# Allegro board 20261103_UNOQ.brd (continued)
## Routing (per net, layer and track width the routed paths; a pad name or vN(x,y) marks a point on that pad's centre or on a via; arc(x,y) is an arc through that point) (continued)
VBAT: length 0.4
  TOP w0.203: 45.73,16.05 45.73,16.34 R603.2
  vias: v1(7.4,14.04) v1(7.4,13.81) v1(7.4,13.56) v1(7.62,40.3) v1(7.62,40.04) v1(7.62,39.79) v1(7.62,14.04) v1(7.62,13.81) v1(7.62,13.56) v1(7.87,40.3) v1(7.87,40.04) v1(7.87,39.79) v1(7.85,14.04) v1(7.85,13.81) v1(7.85,13.56) v1(8.13,40.3) v1(8.13,40.04) v1(8.13,39.79) v1(8.11,14.04) v1(8.11,13.81) v1(8.11,13.56) v2(45.72,15.72) v2(45.72,15.46) v2(45.73,15.23) v2(45.97,15.72) v2(45.97,15.46) v2(45.98,15.23) v2(46.19,15.71) v2(46.18,15.46) v2(46.19,15.24) v2(46.43,15.71) v2(46.42,15.46) v2(46.43,15.24) v3(45.72,15.72) v3(45.72,15.46) v3(45.73,15.23) v3(45.97,15.72) v3(45.97,15.46) v3(45.98,15.23) v3(46.19,15.71) v3(46.18,15.46) v3(46.19,15.24) v3(46.43,15.71) v3(46.42,15.46) v3(46.43,15.24) v4(6.49,40.57) v4(6.49,40.12) v4(6.89,40.56) v4(6.89,40.11) v4(7.29,40.56) v4(7.29,40.11) v4(13.89,7.37) v4(14.17,7.06) v4(14.43,6.68) v4(14.86,6.68) v4(15.32,6.68) v4(15.57,7.14) v4(45.85,14.96) v4(46.22,14.96) v4(46.59,14.96) v4(46.74,15.66) v4(46.74,15.3) v4(46.94,14.99) v5(7.62,40.3) v5(7.62,40.04) v5(7.62,39.79) v5(7.87,40.3) v5(7.87,40.04) v5(7.87,39.79) v5(8.13,40.3) v5(8.13,40.04) v5(8.13,39.79) v5(14.4,7.54) v5(14.43,7.26) v5(14.58,7.01) v5(14.68,7.52) v5(14.68,7.26) v5(14.81,7.01) v5(14.94,7.52) v5(14.94,7.26) v5(15.04,7.01) v5(15.19,7.52) v5(15.19,7.26) v5(15.29,7.01)
VBAT_CONN_VSNS_P: length 7.3
  S3 w0.064: v3(40.51,14.85) 43.82,14.85 45.11,16.14 46.52,16.14 46.61,16.23 46.61,16.46 46.53,16.54 46.36,16.54 46.29,16.47 v3(46.29,16.4)
VBUS_DIV8: length 4
  TOP w0.254: v3(33.06,51.55) 33.22,51.38 R3020.1 R3019.2
  G2 w0.203: v3(34.77,52.2) 34.82,52.25 34.92,52.25 v2(34.98,52.3)
  S3 w0.203: v3(33.06,51.55) 32.94,51.44 v4(32.94,51.16) ; v3(34.77,52.2) 34.62,52.04 v4(34.62,51.94)
  S6 w0.254: v4(32.94,51.16) 33.73,51.94 v4(34.62,51.94)
VBUS_POWER_SWITCH_DISABLE_N: length 47.9
  TOP w0.066: JCTL1.10 43.79,55.16 44.54,54.41 44.54,50.51 v3(44.34,50.31)
  S3 w0.064: v4(13.8,39.21) 15.06,37.95 17.76,37.95 18.3,37.41 19.88,37.41 v4(19.97,37.5) ; v3(44.34,50.31) 44.34,48.12 v4(43.48,47.26)
  S6 w0.064: v4(19.97,37.5) 19.97,38.21 22.15,40.39 33.25,40.39 34.65,41.78 36.58,41.78 37.46,42.66 39.29,42.66 41.58,44.95 41.58,45.31 43.48,47.21 v4(43.48,47.26) ; v5(14.05,39.07) 13.9,39.21 v4(13.8,39.21)
  G7 w0.064: v1(12.23,39.19) 12.79,38.63 13.61,38.63 v5(14.05,39.07)
AMUX_1_TP: length 6.5
  S3 w0.064: v3(39.66,8.85) 39.66,9.84 40.09,10.27 40.09,13.52 39.64,13.97 39.64,14.33 39.24,14.73 v3(39.24,14.81)
ANT_CH0: length 5.6
  TOP w0.066: ANT1.1 15.71,63.59 15.88,63.42 18.89,63.42 19.36,62.95 U2901.2
AUX_CTRL_1: length 13.1
  TOP w0.066: U3001.G1 34.32,51.54 33.83,51.05 v3(33.83,50.23) R3001.1 ; R3003.1 34.93,58.64 34.61,58.96 v3(34.2,58.96)
  S3 w0.064: v3(34.2,58.96) 33.84,58.61 33.84,58.02 33.4,57.58 33.4,56.18 32.55,55.32 32.55,52.56 33.32,51.78 33.32,50.75 33.83,50.24 v3(33.83,50.23)
AUX_CTRL_2: length 15.6
  TOP w0.066: 36.79,57.5 36.79,57.03 36.49,56.74 35.08,56.74 34.37,57.45 34.37,58.16 v3(34.09,58.44) ; U3001.H1 34.57,50.86 34.54,50.83 R3002.1 34.52,49.86 v3(34.14,50.24)
  S3 w0.064: v3(34.14,50.24) 33.5,50.88 33.5,51.93 32.72,52.71 32.72,55.28 33.53,56.09 33.53,57.48 34.09,58.03 v3(34.09,58.44)
BAT_ID: length 8
  S3 w0.064: v3(38.89,8.86) 38.89,9.05 38.74,9.19 38.75,9.2 38.75,9.8 v3(38.93,9.99) 39.55,9.99 39.95,10.39 39.95,13.48 39.48,13.95 39.48,14.33 39.18,14.63 39.12,14.63 38.69,15.06 v3(38.69,15.41)
BAT_THERM: length 6.8
  S3 w0.064: v3(39.26,14.28) 39.26,13.97 39.8,13.43 39.8,10.52 39.52,10.24 38.74,10.24 v3(38.5,10) 38.63,9.87 38.63,9.25 38.4,9.02 v3(38.4,8.85)
BOOT_CAP: length 5.1
  TOP w0.15: v2(40.95,14.28) 40.96,14.27 41.36,14.27 41.65,13.98 43.32,13.98 v2(43.36,14.01)
  G2 w0.2: v2(40.95,14.28) 40.97,14.3 41.36,14.3 41.65,14.01 v2(43.36,14.01)
BOOT_CONFIG0: length 2.7
  TOP w0.066: SOC1.AH9 22.97,36.88 R1304.1 R1303.2
BOOT_CONFIG1: length 2.4
  TOP w0.066: SOC1.AJ7 23.73,38.12 22.88,38.12 R1306.1 R1305.2
BOOT_CONFIG2: length 2.9
  TOP w0.066: R1307.2 R1308.1 22.88,37.55 23.37,37.55 23.89,37.03 24.32,37.03 SOC1.AH8
BOOT_CONFIG3: length 2.9
  TOP w0.066: R1309.2 R1310.1 22.86,38.68 23.5,38.68 24.1,38.08 SOC1.AH6
CBLPWR_N: length 5.4
  TOP w0.066: PMIC1.T10 36.65,14.56 v3(36.65,14.55)
  S3 w0.064: v3(36.65,14.55) 36.65,14.18 36.25,13.78 36.25,12.34 36.1,12.19 36.1,11.4 36.19,11.31 36.19,10.45 36.2,10.44 36.33,10.3 36.56,10.3 v3(36.93,9.93)
CC_OUT: length 4.2
  S3 w0.064: v3(35.28,21.95) 35.74,21.95 35.84,21.84 35.84,18.45 35.86,18.43 v3(35.86,18.24)
CCI_I2C_SCL0: length 29.7
  S3 w0.064: v4(13.96,52.83) 13.96,51.38 13.76,51.18 13.76,49.09 12.68,48.01 12.68,41.99 16.53,38.14 17.85,38.14 18.4,37.59 19.57,37.59 19.91,37.93 25.62,37.93 v3(26.17,38.48)
  S6 w0.064: v4(13.96,52.83) 14.18,53.05 v1(15.7,53.05)
  BOTTOM w0.066: R2607.1 15.35,53.4 v1(15.7,53.05)
CCI_I2C_SCL0_CONN: length 2.5
  BOTTOM w0.066: R2607.2 D26051.2 13.79,53.72 13.34,54.17 JMEDIA1.51
CCI_I2C_SCL1: length 47.6
  S3 w0.064: v4(14.05,58.79) 14.4,58.43 14.4,53.26 16.38,51.28 16.38,45.65 18.85,43.18 20.75,43.18 22.86,41.07 25.7,41.07 26.97,39.8 v3(26.97,39.68)
  S6 w0.064: v1(29.06,61.74) 28.57,61.74 26.57,59.75 26.57,57.86 26.03,57.31 14.62,57.31 14.32,57.62 14.32,58.48 14.05,58.75 v4(14.05,58.79)
  BOTTOM w0.066: R2611.1 30.19,62 R2610.1 29.31,62 29.06,61.76 v1(29.06,61.74)
CCI_I2C_SCL1_CONN: length 3.3
  BOTTOM w0.066: R2611.2 30.77,61.93 D26049.2 30.77,60.66 31.11,60.31 JMEDIA1.24
CCI_I2C_SDA0: length 27.8
  S3 w0.064: v3(26.17,38.88) 25.94,38.65 25.94,38.42 25.62,38.1 19.83,38.1 19.47,37.74 18.52,37.74 17.93,38.33 16.64,38.33 12.84,42.13 12.84,47.9 13.96,49.02 13.96,51.12 14.18,51.34 14.18,52.3 v4(14.36,52.48)
  S6 w0.064: v4(14.36,52.48) 14.4,52.48 v1(14.76,52.83)
  BOTTOM w0.066: R2608.1 14.75,52.84 v1(14.76,52.83)
CCI_I2C_SDA0_CONN: length 3.3
  BOTTOM w0.066: R2608.2 12.92,52.84 12.51,53.25 D26050.2 12.51,53.86 12.06,54.3 12.06,54.95
CCI_I2C_SDA1: length 49.7
  S3 w0.064: v3(26.57,38.88) 26.77,39.09 26.77,39.78 25.65,40.89 22.83,40.89 20.71,43.02 19.76,43.02 19.75,43.03 18.75,43.03 16.21,45.57 16.21,51.21 14.22,53.19 14.22,58.13 v4(14,58.36)
  S6 w0.064: v4(14,58.36) 14.16,58.19 14.16,57.55 14.54,57.17 26.12,57.17 26.7,57.75 26.7,59.67 28.48,61.45 v1(28.7,61.45)
  BOTTOM w0.066: v1(28.7,61.45) 28.7,61.73 28.94,61.97 29.06,61.97 29.48,62.39 30.62,62.39 30.77,62.54 R2609.1 31.08,62.74 R2612.1
CCI_I2C_SDA1_CONN: length 3.6
  BOTTOM w0.066: R2612.2 D26048.2 31.32,60.53 32.38,59.47 32.38,58.85
CDC_CP_FLY_N: length 2
  TOP w0.2: C501.2 42.19,19.59 41.52,18.91 PMIC1.A27 PMIC1.B26
CDC_CP_FLY_P: length 2.3
  TOP w0.2: C501.1 42.24,20.09 PMIC1.A25
CDC_CP_VNEG: length 2.9
  TOP w0.2: PMIC1.C27 41.73,18.24 42.16,18.68 42.61,18.68 43.18,19.25 C502.1 43.95,19.25 F501.1
CDC_PA_VNEG: length 4.7
  TOP w0.16: PMIC1.K24 40.67,17.25 40.82,17.4 41.23,17.4 ; PMIC1.F26 41.65,17.39 42.49,18.23 C503.1
  TOP w0.2: 41.23,17.4 PMIC1.F26 ; F501.2 43.91,18.23 C503.1
CSI0_A0_CLK_M: length 25.4
  TOP w0.058: SOC1.N2 30.65,39.68 v3(30.66,39.69)
  S3 w0.053: v3(30.66,39.69) 30.9,39.93 30.9,40.27 30.8,40.37 30.8,41.22 29.6,42.42 28.12,42.42 27.58,42.95 27.58,43.36 v4(27.76,43.54)
  S6 w0.053: v4(27.76,43.54) 27.76,43.77 v1(27.69,43.85)
  BOTTOM w0.058: JMEDIA1.33 24.26,54.95 24.2,54.89 24.2,53.97 24.3,53.88 25.14,53.88 25.32,53.69 25.32,53.31 U2610.7 U2610.4 25.35,52.08 25.35,51.57 27.59,49.33 27.59,48.83 27.45,48.7 26.9,48.7 26.84,48.64 26.84,48.52 26.9,48.46 27.45,48.46 27.59,48.32 27.59,48.1 27.45,47.96 26.9,47.96 26.84,47.9 26.84,47.78 26.9,47.73 27.45,47.73 27.59,47.59 27.59,47.36 27.45,47.22 26.9,47.22 26.84,47.16 26.84,47.05 26.9,46.99 27.45,46.99 27.59,46.85 27.59,46.62 27.45,46.49 26.9,46.49 26.84,46.43 26.84,46.31 26.9,46.25 27.45,46.25 27.59,46.12 27.59,44.18 27.69,44.08 v1(27.69,43.85)
CSI0_A1_LN1_P: length 25.2
  TOP w0.058: v3(30.27,39.61) 30.2,39.68 30.17,39.68
  S3 w0.05: 30.29,39.65 30.28,39.63
  S3 w0.053: 30.29,39.65 30.29,39.72 30.31,39.74 30.31,41.11 29.39,42.04 27.94,42.04 26.5,43.47 26.5,43.67 v4(26.32,43.85)
  S3 w0.058: 30.28,39.63 30.27,39.62 v3(30.27,39.61)
  S6 w0.053: v4(26.32,43.85) 26.32,44.11 26.34,44.13 v1(26.39,44.13) ; v1(26.61,52.17) 26.72,52.07 26.72,51.7 26.66,51.65 26.24,51.65 26.19,51.7 26.19,51.79 26.14,51.84 26.03,51.84 25.98,51.79 25.98,51.7 25.92,51.65 25.82,51.65 25.76,51.7 25.76,51.79 25.71,51.84 25.6,51.84 25.55,51.79 25.55,51.7 25.5,51.65 25.17,51.65 24.99,51.47 24.99,50.94 v1(24.88,50.83)
  BOTTOM w0.058: v1(24.88,50.83) 24.98,50.73 24.98,49.33 24.92,49.27 24.58,49.27 24.44,49.13 24.44,48.91 24.58,48.77 24.92,48.77 24.98,48.71 24.98,48.59 24.92,48.53 24.58,48.53 24.44,48.4 24.44,48.17 24.58,48.03 24.92,48.03 24.98,47.97 24.98,47.86 24.92,47.8 24.58,47.8 24.44,47.66 24.44,47.43 24.58,47.3 24.92,47.3 24.98,47.24 24.98,46.68 26.48,45.18 26.48,44.22 v1(26.39,44.13) ; v1(26.61,52.17) 26.58,52.17 U2610.2 U2610.9 26.69,53.29 26.69,53.68 26.88,53.87 27.81,53.87 27.87,53.93 27.87,54.89 27.81,54.95 27.3,54.95
CSI0_A2_LN2_M: length 25.1
  S3 w0.05: 29.78,39.83 v3(29.78,39.68)
  S3 w0.053: 29.78,39.83 29.71,39.9 29.71,39.9 29.6,40.01 29.6,40.18 29.7,40.27 29.7,40.3 29.7,40.3 29.7,40.9 29.11,41.49 27.59,41.49 26.37,42.71 24.9,42.71 24.2,43.41 24.2,43.81 24.19,43.82 v4(24.02,43.82)
  S6 w0.053: v1(18.12,50.42) 18.23,50.53 18.61,50.53 19.2,51.12 19.2,52.05 v1(19.39,52.24) ; v4(24.02,43.82) 24.02,44.08 24.08,44.13 v1(24.11,44.1)
  BOTTOM w0.058: JMEDIA1.39 20.45,54.95 20.39,54.89 20.39,53.88 20.25,53.74 19.32,53.74 19.2,53.62 19.2,53.31 U2609.10 v1(19.39,52.24) ; v1(18.12,50.42) 18.22,50.52 18.65,50.52 24.21,44.96 24.21,44.19 v1(24.11,44.1)
CSI0_B0_LN0_P: length 25.4
  S3 w0.05: 31.07,40.44 31.07,40.43 31.08,40.43 31.08,39.8 30.85,39.58 30.85,39.21 30.78,39.14 30.71,39.14 v3(30.57,39.28)
  S3 w0.053: 31.07,40.44 31.07,41.2 29.7,42.58 29.02,42.58 28.52,43.08 28.52,43.36 v4(28.35,43.54)
  S6 w0.053: v4(28.35,43.54) 28.35,43.79 28.4,43.85 v1(28.44,43.85)
  BOTTOM w0.058: v1(28.44,43.85) 28.44,44.08 28.54,44.18 28.54,46.85 29.9,48.21 29.9,48.29 29.6,48.58 29.6,48.77 29.77,48.94 29.96,48.94 30.25,48.65 30.34,48.65 30.42,48.73 30.42,48.81 30.13,49.1 30.13,49.3 30.29,49.46 30.48,49.46 30.77,49.17 30.86,49.17 30.94,49.25 30.94,49.33 30.65,49.62 30.65,49.82 30.81,49.98 31,49.98 31.29,49.69 31.38,49.69 31.46,49.77 31.46,49.85 31.17,50.14 31.17,50.34 31.33,50.5 31.52,50.5 31.82,50.21 31.9,50.21 32.2,50.51 32.2,50.59 32.16,50.63 32.16,50.72 32.24,50.8 32.32,50.8 32.36,50.76 32.45,50.76 32.8,51.11 32.8,51.79 32.63,51.96 U2606.5 U2606.6 32.81,53.29 32.81,53.63 32.7,53.74 31.86,53.74 31.68,53.92 31.68,54.89 31.62,54.95 JMEDIA1.23
CSI0_B1_LN1_M: length 25.1
  TOP w0.058: v3(30.22,39.2) 30.17,39.25 30.17,39.28
  S3 w0.05: v3(30.22,39.2) 30.22,39.3 30.46,39.54 30.46,39.71
  S3 w0.053: 30.46,39.71 30.43,39.74 30.43,41.16 29.44,42.15 27.99,42.15 26.62,43.52 26.62,43.67 v4(26.8,43.85)
  S6 w0.053: v1(25.21,50.83) 25.11,50.93 25.11,51.42 25.22,51.53 26.71,51.53 26.83,51.65 26.83,52.07 v1(26.94,52.17) ; v1(26.71,44.13) 26.75,44.16 26.8,44.11 v4(26.8,43.85)
  BOTTOM w0.058: v1(26.94,52.17) U2610.1 U2610.10 26.82,53.31 26.82,53.62 26.94,53.74 27.87,53.74 28.01,53.88 28.01,54.89 28.07,54.95 JMEDIA1.27 ; v1(26.71,44.13) 26.62,44.22 26.62,45.23 25.11,46.74 25.11,47.29 24.97,47.43 24.63,47.43 24.57,47.49 24.57,47.6 24.63,47.66 24.97,47.66 25.11,47.8 25.11,48.03 24.97,48.17 24.63,48.17 24.57,48.22 24.57,48.34 24.63,48.4 24.97,48.4 25.11,48.54 25.11,48.77 24.97,48.9 24.63,48.9 24.57,48.96 24.57,49.08 24.63,49.14 24.97,49.14 25.11,49.27 25.11,50.73 v1(25.21,50.83)
CSI0_B2_LN3_P: length 25.3
  S3 w0.05: 29.97,40.44 29.97,40.43 29.97,40.43 29.97,39.49 v3(29.77,39.28)
  S3 w0.053: 29.97,40.44 29.97,41.03 29.24,41.77 27.71,41.77 26.48,43 25.58,43 25.38,43.19 25.38,43.65 v4(25.18,43.84)
  S6 w0.053: v4(25.18,43.84) 25.26,43.92 v1(25.26,44.13)
  BOTTOM w0.058: v1(25.26,44.13) 25.36,44.23 25.36,44.41 25.3,44.47 25.21,44.47 25.15,44.53 25.15,44.64 25.21,44.7 25.3,44.7 25.36,44.76 25.36,45.05 25.06,45.35 24.97,45.35 24.95,45.33 24.86,45.33 24.78,45.41 24.78,45.49 24.81,45.52 24.81,45.6 19.14,51.27 17.8,51.27 17.57,51.49 17.57,51.8 17.39,51.98 U2609.5 U2609.6 17.57,53.29 17.57,53.63 17.46,53.74 16.62,53.74 16.44,53.92 16.44,54.89 16.38,54.95 JMEDIA1.47
CSI0_C0_LN0_M: length 25.3
  S3 w0.05: v3(30.57,38.88) 30.71,39.03 30.83,39.03 30.97,39.16 30.97,39.54 31.19,39.76 31.19,40.43 31.19,40.43 31.19,40.44
  S3 w0.053: 31.19,40.44 31.19,41.25 29.74,42.7 29.07,42.7 28.64,43.13 28.64,43.37 28.81,43.54 v4(28.82,43.54)
  S6 w0.053: v1(28.77,43.85) 28.82,43.79 v4(28.82,43.54)
  BOTTOM w0.058: v1(28.77,43.85) 28.77,44.08 28.67,44.18 28.67,46.79 30.03,48.15 30.03,48.34 29.74,48.64 29.74,48.72 29.82,48.8 29.9,48.8 30.2,48.51 30.39,48.51 30.55,48.67 30.55,48.87 30.26,49.16 30.26,49.24 30.34,49.32 30.43,49.32 30.72,49.03 30.91,49.03 31.07,49.19 31.07,49.39 30.78,49.68 30.78,49.76 30.86,49.84 30.95,49.84 31.24,49.55 31.43,49.55 31.59,49.71 31.59,49.91 31.3,50.2 31.3,50.28 31.39,50.37 31.47,50.37 31.76,50.07 31.95,50.07 32.94,51.06 32.94,51.8 33.13,51.99 U2606.4 U2606.7 32.94,53.31 32.94,53.69 32.76,53.88 31.91,53.88 31.82,53.97 31.82,54.89 31.88,54.95 32.38,54.95
CSI0_C1_LN2_P: length 25.1
  S3 w0.053: v4(24.5,43.82) 24.33,43.82 24.32,43.81 24.32,43.46 24.95,42.83 26.41,42.83 27.64,41.61 29.16,41.61 29.82,40.94 29.82,40.25 29.82,40.23 29.78,40.19 v3(29.78,40.08)
  S6 w0.053: v4(24.5,43.82) 24.5,44.08 24.48,44.1 v1(24.44,44.1) ; v1(18.12,50.75) 18.22,50.65 18.56,50.65 18.73,50.81 18.73,50.89 18.66,50.96 18.66,51.03 18.74,51.11 18.81,51.11 18.88,51.04 18.95,51.04 19.08,51.17 19.08,51.55 19.03,51.6 18.95,51.6 18.9,51.66 18.9,51.76 18.95,51.82 19.03,51.82 19.08,51.87 19.08,52.05 v1(18.89,52.24)
  BOTTOM w0.058: v1(18.12,50.75) 18.21,50.65 18.71,50.65 24.34,45.02 24.34,44.19 v1(24.44,44.1) ; v1(18.89,52.24) U2609.9 19.07,53.29 19.07,53.68 19.26,53.87 20.19,53.87 20.25,53.93 20.25,54.89 20.19,54.95 19.68,54.95
CSI0_C2_LN3_M: length 25.3
  S3 w0.05: 30.09,40.44 30.09,40.43 30.09,40.43 30.09,39.44 30.02,39.37 30.02,39.13 v3(29.77,38.88)
  S3 w0.053: 30.09,40.44 30.09,41.08 29.29,41.88 27.76,41.88 26.53,43.11 25.63,43.11 25.5,43.24 25.5,43.68 v4(25.66,43.84)
  S6 w0.053: v1(25.59,44.13) 25.59,43.91 v4(25.66,43.84)
  BOTTOM w0.058: 17.14,54.95 16.64,54.95 16.58,54.89 16.58,53.97 16.68,53.88 17.52,53.88 17.7,53.69 17.7,53.31 U2609.7 U2609.4 17.89,51.97 17.71,51.79 17.71,51.55 17.86,51.4 19.2,51.4 25.49,45.11 25.49,44.23 v1(25.59,44.13)
CSI0_NC_CLK_P: length 25.5
  TOP w0.058: SOC1.N1 30.65,40.08 v3(30.66,40.09)
  S3 w0.053: v3(30.66,40.09) 30.68,40.11 30.68,41.18 29.56,42.3 28.07,42.3 27.45,42.92 27.45,43.02 27.43,43.05 27.34,43.05 27.32,43.08 27.32,43.21 27.34,43.24 27.43,43.24 27.47,43.28 27.47,43.39 27.31,43.55 v4(27.26,43.55)
  S6 w0.053: v1(27.36,43.85) 27.36,43.65 v4(27.26,43.55)
  BOTTOM w0.058: JMEDIA1.35 24,54.95 24.06,54.89 24.06,53.92 24.24,53.74 25.08,53.74 25.19,53.63 25.19,53.29 U2610.6 U2610.5 25.22,52.04 25.22,51.51 25.86,50.87 25.86,50.78 25.8,50.72 25.8,50.64 25.89,50.55 25.97,50.55 26.03,50.62 26.11,50.62 27.45,49.28 27.45,48.89 27.4,48.83 26.85,48.83 26.71,48.69 26.71,48.46 26.85,48.33 27.4,48.33 27.45,48.27 27.45,48.15 27.4,48.09 26.85,48.09 26.71,47.96 26.71,47.73 26.85,47.59 27.4,47.59 27.45,47.53 27.45,47.42 27.4,47.36 26.85,47.36 26.71,47.22 26.71,46.99 26.85,46.85 27.4,46.85 27.45,46.8 27.45,46.68 27.4,46.62 26.85,46.62 26.71,46.48 26.71,46.26 26.85,46.12 27.4,46.12 27.45,46.06 27.45,44.18 27.36,44.08 v1(27.36,43.85)
CSI1_A0_CLK_M: length 56.6
  TOP w0.058: SOC1.T2 29.12,39.93 29.12,39.93 29.06,39.99 v3(29.06,40.01)
  S3 w0.053: v4(19.96,61.72) 20.15,61.53 20.15,61.23 20.1,61.17 16.59,61.17 16.47,61.05 16.47,60.85 16.59,60.73 20.1,60.73 20.15,60.67 20.15,60.57 20.1,60.51 16.59,60.51 16.47,60.39 16.47,60.19 16.59,60.07 20.1,60.07 20.15,60.01 20.15,59.91 20.1,59.85 16.59,59.85 16.47,59.73 16.47,59.53 16.59,59.41 20.1,59.41 20.15,59.35 20.15,58.87 19.76,58.48 19.69,58.48 19.48,58.69 19.31,58.69 19.16,58.54 19.16,58.37 19.37,58.16 19.37,58.09 19.3,58.01 19.22,58.01 19.01,58.22 18.84,58.22 18.7,58.08 18.7,57.9 18.91,57.7 18.91,57.62 18.26,56.98 18.26,54.09 19.85,52.5 19.85,46.17 21.13,44.89 21.32,44.89 24.13,42.09 26.14,42.09 27.52,40.7 28.6,40.7 29.06,40.24 v3(29.06,40.01)
  S6 w0.053: v1(19.94,62.21) 20.13,62.02 20.13,61.89 v4(19.96,61.72)
  BOTTOM w0.058: v1(19.94,62.21) U2607.1 U2607.6 19.94,60.57 20.13,60.38 20.13,59.8 19.68,59.35 19.68,58.85
CSI1_A1_LN1_P: length 56.4
  S3 w0.051: v3(29.05,39.65) 29.05,39.55 29.01,39.51 28.9,39.51 28.85,39.56 28.85,40.27 28.61,40.51 28.43,40.51
  S3 w0.053: v4(15.62,61.38) 15.44,61.2 15.44,61 15.49,60.95 15.54,60.95 15.59,60.9 15.59,60.79 15.54,60.74 15.49,60.74 15.44,60.68 15.44,60.39 15.96,59.87 15.96,58.97 16.17,58.76 17.53,58.76 17.67,58.62 17.67,58.41 17.55,58.29 16.13,58.29 16.09,58.25 16.09,58.12 16.13,58.08 17.64,58.08 17.75,57.97 17.75,57.74 17.63,57.62 16.11,57.62 16.06,57.57 16.06,57.46 16.11,57.41 17.63,57.41 17.75,57.29 17.75,57.08 17.63,56.96 16.11,56.96 16.06,56.91 16.06,56.8 16.11,56.75 17.63,56.75 17.75,56.63 17.75,56.42 17.63,56.3 16.11,56.3 16.06,56.25 16.06,56.14 16.11,56.09 17.63,56.09 17.75,55.97 17.75,55.76 17.63,55.64 16.11,55.64 16.06,55.59 16.06,55.48 16.11,55.43 17.63,55.43 17.75,55.31 17.75,55.1 17.63,54.98 16.11,54.98 16.06,54.93 16.06,54.82 16.11,54.77 17.45,54.77 17.57,54.65 17.57,54.44 17.45,54.32 16.11,54.32 16.06,54.27 16.06,54 18.03,52.03 18.03,47.33 20.8,44.56 21.3,44.56 23.91,41.95 26.09,41.95 27.53,40.51 28.43,40.51
  S6 w0.053: v4(15.62,61.38) v1(15.62,61.66)
  BOTTOM w0.058: 17.14,58.85 16.64,58.85 16.58,58.9 16.58,59.88 16.31,60.15 15.57,60.15 15.43,60.29 15.43,60.6 U2605.6 v1(15.62,61.66)
CSI1_A2_LN2_M: length 56.6
  S3 w0.053: v4(13.99,60.61) 14.18,60.42 14.18,60.23 15.3,59.11 15.3,53.8 17.42,51.68 17.42,46.88 20.33,43.97 21.06,43.97 23.47,41.56 25.9,41.56 27.57,39.89 28.36,39.89 v3(28.5,39.75)
  S6 w0.053: v1(25.05,62.35) 25.18,62.48 25.18,62.65 25.02,62.81 24.26,62.81 24.01,62.56 24.01,62.45 24.75,61.7 24.75,61.52 24.61,61.38 24.44,61.38 23.64,62.18 23.56,62.18 23.48,62.11 23.48,62.04 24.29,61.24 24.29,61.06 24.14,60.91 23.98,60.91 23.17,61.72 23.09,61.72 23.01,61.64 23.01,61.57 23.82,60.77 23.82,60.59 23.67,60.44 23.51,60.44 22.71,61.25 22.62,61.25 22.55,61.17 22.55,61.11 23.35,60.3 23.35,60.12 23.21,59.98 23.04,59.98 22.35,60.67 22.28,60.67 21.61,60 14.43,60 14.17,60.26 14.17,60.43 v4(13.99,60.61)
  BOTTOM w0.058: JMEDIA1.36 24,58.85 24.06,58.9 24.06,59.95 25.24,61.13 25.24,61.25 25.05,61.44 U2608.10 v1(25.05,62.35) U2608.1
CSI1_B0_LN0_P: length 56.5
  S3 w0.05: 29.39,39.3 v3(29.37,39.28)
  S3 w0.053: 29.39,39.3 29.39,39.35 29.37,39.36 29.37,40.3 29.46,40.38 29.46,40.71 28.94,41.22 27.41,41.22 26.24,42.39 24.47,42.39 21.51,45.35 21.32,45.35 20.36,46.31 20.36,52.76 18.91,54.21 18.91,56.76 21.79,59.64 21.79,59.92 21.74,59.97 21.12,59.97 21,60.09 21,60.3 21.12,60.42 22.07,60.42 22.13,60.47 22.13,60.58 22.07,60.63 21.12,60.63 21,60.75 21,60.96 21.12,61.08 22.65,61.08 22.7,61.13 22.7,61.24 22.65,61.29 21.43,61.29 21.3,61.42 21.3,61.63 21.41,61.74 22.65,61.74 22.7,61.79 22.7,62.15 22.6,62.25 22.32,62.25 22.2,62.37 22.2,62.95 22.15,63.01 22.04,63.01 21.99,62.95 21.99,62.37 21.87,62.25 21.66,62.25 21.54,62.37 21.54,62.95 21.49,63.01 21.38,63.01 21.33,62.95 21.33,62.37 21.21,62.25 21,62.25 20.88,62.37 20.88,62.95 20.83,63.01 20.72,63.01 20.67,62.95 20.67,62.37 20.55,62.25 15.76,62.25 15.71,62.2 15.71,62.1 15.65,62.05 15.55,62.05 15.49,62.1 15.49,62.2 15.44,62.25 15.33,62.25 15.28,62.2 15.28,62.1 15.23,62.05 15.12,62.05 15.07,62.1 15.07,62.2 15.01,62.25 14.91,62.25 14.85,62.2 14.85,62.1 14.8,62.05 14.69,62.05 14.64,62.1 14.64,62.2 14.59,62.25 14.26,62.25 13.94,61.93 13.94,61.52 v4(14.12,61.34)
  S6 w0.053: v4(14.12,61.34) v1(14.12,61.66)
  BOTTOM w0.058: JMEDIA1.52 12.83,58.85 12.77,58.9 12.77,59.87 12.9,60 13.72,60 13.94,60.22 13.94,60.6 U2605.9 v1(14.12,61.66)
CSI1_B1_LN1_M: length 56.5
  S3 w0.051: v3(29.05,39.25) 29.05,39.35 29,39.4 28.85,39.4 28.74,39.51 28.74,40.22 28.57,40.39 28.43,40.39
  S3 w0.053: v4(15.14,61.38) 15.32,61.2 15.32,60.34 15.84,59.82 15.84,58.92 16.12,58.64 17.48,58.64 17.55,58.58 17.55,58.46 17.5,58.41 16.09,58.41 15.97,58.3 15.97,58.07 16.08,57.96 17.59,57.96 17.63,57.92 17.63,57.79 17.58,57.74 16.06,57.74 15.94,57.62 15.94,57.41 16.06,57.29 17.58,57.29 17.63,57.24 17.63,57.13 17.58,57.08 16.06,57.08 15.94,56.96 15.94,56.75 16.06,56.63 17.58,56.63 17.63,56.58 17.63,56.47 17.58,56.42 16.06,56.42 15.94,56.3 15.94,56.09 16.06,55.97 17.58,55.97 17.63,55.92 17.63,55.81 17.58,55.76 16.06,55.76 15.94,55.64 15.94,55.43 16.06,55.31 17.58,55.31 17.63,55.26 17.63,55.15 17.58,55.1 16.06,55.1 15.94,54.98 15.94,54.77 16.06,54.65 17.4,54.65 17.45,54.6 17.45,54.49 17.4,54.44 16.06,54.44 15.94,54.32 15.94,53.95 17.91,51.98 17.91,47.28 20.75,44.44 21.25,44.44 23.86,41.83 26.04,41.83 27.48,40.39 28.43,40.39
  S6 w0.053: v4(15.14,61.38) 15.14,61.63 v1(15.12,61.66)
  BOTTOM w0.058: JMEDIA1.48 16.38,58.85 16.44,58.9 16.44,59.83 16.25,60.02 15.51,60.02 15.3,60.23 15.3,60.6 U2605.7 v1(15.12,61.66)
CSI1_B2_LN3_P: length 56.8
  S3 w0.053: v4(12.86,60.51) 13.03,60.33 13.43,60.33 14.91,58.85 14.91,53.54 16.96,51.49 16.96,46.66 20.09,43.53 21.04,43.53 23.16,41.4 25.86,41.4 28.12,39.14 28.43,39.14 v3(28.57,39.28)
  S6 w0.053: v4(12.86,60.51) 13.04,60.33 13.43,60.33 15.09,58.66 15.09,58.07 15.36,57.8 25.21,57.8 25.62,58.21 25.62,59.71 26.61,60.7 26.61,60.77 26.59,60.79 26.59,60.87 26.67,60.95 26.74,60.95 26.76,60.92 26.84,60.92 26.91,61 26.91,61.07 26.89,61.1 26.89,61.17 26.97,61.25 27.04,61.25 27.06,61.23 27.14,61.23 27.52,61.61 27.52,61.7 27.47,61.75 27.38,61.75 27.33,61.81 27.33,61.91 27.38,61.97 27.47,61.97 27.52,62.02 27.52,62.63 27.35,62.81 26.91,62.81 26.86,62.75 26.86,62.56 27.05,62.37 v1(27.05,62.34)
  BOTTOM w0.058: JMEDIA1.28 28.07,58.85 28.01,58.9 28.01,59.94 26.86,61.09 26.86,61.26 27.05,61.45 U2608.6 v1(27.05,62.34) U2608.5
CSI1_C0_LN0_M: length 56.6
  S3 w0.05: v3(29.37,38.88) 29.54,39.06 29.54,39.21
  S3 w0.053: 29.54,39.21 29.54,39.21 29.54,39.36 29.49,39.41 29.49,40.25 29.57,40.34 29.57,40.76 28.99,41.34 27.45,41.34 26.29,42.51 24.52,42.51 21.56,45.47 21.37,45.47 20.48,46.36 20.48,52.81 19.03,54.26 19.03,56.71 21.91,59.59 21.91,59.97 21.79,60.09 21.17,60.09 21.12,60.14 21.12,60.25 21.17,60.3 22.12,60.3 22.25,60.42 22.25,60.63 22.12,60.75 21.17,60.75 21.12,60.8 21.12,60.91 21.17,60.96 22.7,60.96 22.82,61.08 22.82,61.29 22.7,61.41 21.48,61.41 21.42,61.47 21.42,61.58 21.46,61.62 22.7,61.62 22.82,61.74 22.82,62.2 22.65,62.37 22.37,62.37 22.32,62.42 22.32,63 22.2,63.12 21.99,63.12 21.87,63 21.87,62.42 21.82,62.37 21.71,62.37 21.66,62.42 21.66,63 21.54,63.12 21.33,63.12 21.21,63 21.21,62.42 21.16,62.37 21.05,62.37 21,62.42 21,63 20.88,63.12 20.67,63.12 20.55,63 20.55,62.42 20.5,62.37 14.21,62.37 13.82,61.98 13.82,61.52 v4(13.64,61.34)
  S6 w0.053: v4(13.64,61.34) 13.64,61.63 v1(13.62,61.66)
  BOTTOM w0.058: 12.06,58.85 12.57,58.85 12.63,58.9 12.63,59.92 12.84,60.13 13.66,60.13 13.81,60.28 13.81,60.6 U2605.10 v1(13.62,61.66)
CSI1_C1_LN2_P: length 56.6
  S3 w0.053: v4(14.47,60.61) 14.3,60.44 14.3,60.28 15.42,59.16 15.42,53.85 17.54,51.73 17.54,46.93 20.38,44.09 21.11,44.09 23.52,41.68 25.95,41.68 27.62,40.01 28.36,40.01 v3(28.5,40.15)
  S6 w0.053: v1(25.55,62.35) 25.4,62.35 25.3,62.45 25.3,62.7 25.07,62.93 24.89,62.93 24.79,63.03 24.68,63.03 24.58,62.93 24.22,62.93 23.89,62.61 23.89,62.4 24.64,61.65 24.64,61.57 24.56,61.5 24.49,61.5 23.69,62.3 23.51,62.3 23.36,62.16 23.36,61.99 24.17,61.19 24.17,61.1 24.09,61.03 24.03,61.03 23.22,61.83 23.04,61.83 22.9,61.69 22.9,61.53 23.7,60.72 23.7,60.64 23.63,60.56 23.56,60.56 22.75,61.37 22.57,61.37 22.43,61.22 22.43,61.06 23.23,60.25 23.23,60.17 23.16,60.09 23.09,60.09 22.4,60.78 22.23,60.78 21.56,60.12 14.48,60.12 14.29,60.31 14.29,60.43 v4(14.47,60.61)
  BOTTOM w0.058: U2608.2 v1(25.55,62.35) U2608.9 25.55,61.45 25.37,61.27 25.37,61.07 24.2,59.9 24.2,58.9 24.26,58.85 JMEDIA1.34
CSI1_C2_LN3_M: length 56.8
  S3 w0.053: v3(28.57,38.88) 28.43,39.02 28.42,39.02 28.07,39.02 25.81,41.29 23.12,41.29 20.99,43.41 20.04,43.41 16.84,46.61 16.84,51.44 14.79,53.49 14.79,58.81 13.38,60.22 13.04,60.22 v4(12.86,60.03)
  S6 w0.053: v4(12.86,60.03) 13.03,60.21 13.38,60.21 14.97,58.62 14.97,58.02 15.31,57.68 25.26,57.68 25.74,58.16 25.74,59.66 27.64,61.56 27.64,62.68 27.4,62.92 26.86,62.92 26.74,62.8 26.74,62.53 v1(26.55,62.34)
  BOTTOM w0.058: 27.3,58.85 27.81,58.85 27.87,58.9 27.87,59.89 26.73,61.03 26.73,61.29 26.55,61.47 U2608.7 v1(26.55,62.34) U2608.4
CSI1_NC_CLK_P: length 56.6
  TOP w0.058: SOC1.T1 29.23,40.22 v3(29.23,40.48)
  S3 w0.053: v4(20.44,61.72) 20.27,61.55 20.27,61.18 20.15,61.06 16.64,61.06 16.59,61 16.59,60.9 16.64,60.84 20.15,60.84 20.27,60.72 20.27,60.52 20.15,60.4 16.64,60.4 16.59,60.34 16.59,60.24 16.64,60.18 20.15,60.18 20.27,60.06 20.27,59.86 20.15,59.74 16.64,59.74 16.59,59.68 16.59,59.58 16.64,59.52 20.15,59.52 20.27,59.4 20.27,58.82 19.81,58.36 19.64,58.36 19.43,58.57 19.36,58.57 19.28,58.5 19.28,58.42 19.49,58.21 19.49,58.04 19.35,57.9 19.17,57.9 18.96,58.1 18.89,58.1 18.81,58.03 18.81,57.95 19.02,57.74 19.02,57.57 18.38,56.93 18.38,54.14 19.97,52.55 19.97,46.22 21.18,45.01 21.37,45.01 24.17,42.2 26.18,42.2 27.57,40.82 28.65,40.82 28.76,40.71 28.86,40.71 28.96,40.61 28.96,40.5 29.1,40.36 29.16,40.36 29.23,40.43 v3(29.23,40.48)
  S6 w0.053: v1(20.44,62.21) 20.25,62.02 20.25,61.91 v4(20.44,61.72)
  BOTTOM w0.058: v1(20.44,62.21) U2607.2 U2607.5 20.44,60.53 20.26,60.35 20.26,59.84 20.95,59.15 JMEDIA1.40
DC_IN: length 4.3
  V5 w0.203: 2.54,21.81 JANALOG1.8 ; JANALOG1.8 1.49,22.86 ; JANALOG1.8 2.54,23.91 ; JANALOG1.8 3.59,22.86
  S6 w0.5: 7.12,54.93 v1(7.06,54.99)
  vias: v1(2.55,45.38) v1(2.55,45.13) v1(2.79,45.38) v1(2.79,45.13) v1(3.04,45.38) v1(3.04,45.13) v1(3.28,45.38) v1(3.28,45.13) v1(6.82,55.26) v1(6.82,55) v1(6.82,54.72) v1(7.06,55.25) v1(7.06,54.71) v1(7.3,55.25) v1(7.3,54.99) v1(7.3,54.71) v4(1.67,45.51) v4(1.84,45.14) v4(2.07,45.52) v4(2.25,45.15) v4(6.52,55.24) v4(6.52,54.85) v4(6.85,54.39) v4(6.89,55.55) v4(7.29,55.54) v4(7.27,54.39) v5(2.55,45.38) v5(2.55,45.13) v5(2.79,45.38) v5(2.79,45.13) v5(3.04,45.38) v5(3.04,45.13) v5(3.28,45.38) v5(3.28,45.13) v5(6.82,55.26) v5(6.82,55) v5(6.82,54.72) v5(7.06,55.25) v5(7.06,54.71) v5(7.3,55.25) v5(7.3,54.99) v5(7.3,54.71)
DDR_RESET_N: length 17.1
  TOP w0.066: v3(40.28,27.84) 40.33,27.79 45.72,27.79 45.97,28.04 45.97,31.24 45.86,31.36 DRAM1.T11
  S3 w0.079: v3(34.17,30.08) 34.66,30.08 34.98,29.77 35.38,29.77 36.17,28.98 36.17,28.39 36.19,28.37 36.19,28.35 36.91,27.64 38.95,27.64 39.15,27.84 v3(40.28,27.84)
DRAM_ZQ0: length 0.6
  S3 w0.2: v4(40.65,41.43) v1(40.65,41.11)
  S6 w0.2: v1(40.65,41.11) v4(40.65,41.43)
DRAM_ZQ1: length 0.8
  S3 w0.2: v3(43.06,41.11) v4(43.06,41.39)
  S6 w0.2: v1(43.06,41.95) v4(43.06,41.39)
DSI0_REXT_PLL: length 2.1
  TOP w0.05: SOC1.L30 31.37,28.48 31.37,28.33
  TOP w0.066: R1522.1 30.79,27.34 31.37,27.92 31.37,28.33
DSI1_CLK_M_TP: length 5.5
  S3 w0.05: v3(30.97,29.68) 31.11,29.54
  S3 w0.053: v3(30.14,25.41) 30.14,25.48 30.27,25.61 30.66,25.61 31.6,26.55 31.6,28.35 31.6,28.35 31.6,28.8 31.59,28.81 31.59,28.96 31.6,28.96 31.6,29.2 31.33,29.47 31.29,29.47 31.23,29.54 31.11,29.54
DSI1_CLK_P_TP: length 5.5
  S3 w0.05: v3(30.97,29.28) 31.11,29.42 31.11,29.42
  S3 w0.053: 31.11,29.42 31.18,29.42 31.24,29.36 31.28,29.36 31.48,29.16 31.48,29.01 31.47,29 31.47,28.76 31.48,28.75 31.48,28.3 31.48,28.3 31.48,26.6 31.29,26.4 31.21,26.4 31.18,26.43 31.1,26.43 31.03,26.36 31.03,26.28 31.06,26.25 31.06,26.18 30.98,26.1 30.91,26.1 30.88,26.13 30.8,26.13 30.73,26.06 30.73,25.98 30.76,25.95 30.76,25.88 30.61,25.73 30.27,25.73 30.14,25.85 v3(30.14,25.95)
EAR_M: length 3.6
  S3 w0.15: v3(41.52,17.68) 42.42,17.68 42.88,18.14 v3(44.88,18.14)
EAR_M_R: length 26.8
  TOP w0.2: v3(45.92,18.14) 45.91,18.14 R2671.2
  S3 w0.2: v4(46.36,18.22) 46,18.22 v3(45.92,18.14)
  S6 w0.2: v1(46.76,18.29) 46.69,18.22 v4(46.36,18.22)
  BOTTOM w0.203: v1(46.76,18.29) 46.78,18.31 47.06,18.31 47.36,18.01 47.36,16.2 44.87,13.71 38.19,13.71 37.65,14.25 29.99,14.25 29.54,14.25 28.95,14.25 28.6,13.9 28.18,13.9 D26064.2
  BOTTOM w0.254: D26064.2 27.81,13.18 27.3,12.67 27.3,11.98
EAR_P: length 3.8
  S3 w0.15: v3(41.35,17.96) 42.27,17.96 42.97,18.66 44.84,18.66 v3(44.86,18.68)
EAR_P_R: length 26.7
  TOP w0.254: v3(45.92,18.67) 45.91,18.68 R2670.2
  S3 w0.2: v3(45.92,18.67) 46.32,18.67 v4(46.36,18.7)
  S6 w0.2: v4(46.36,18.7) 46.69,18.7 46.76,18.63 v1(46.76,18.62)
  BOTTOM w0.203: D26063.2 28.83,13.72 29.07,13.96 37.53,13.96 38.07,13.42 44.99,13.42 47.65,16.08 47.65,18.13 47.18,18.6 46.78,18.6 v1(46.76,18.62)
  BOTTOM w0.254: D26063.2 28.83,13.47 28.57,13.22 28.57,11.98
EBI0_CA_0: length 6.1
  TOP w0.084: v3(38.67,36.23) 38.67,36.48 38.6,36.56 38.26,36.56 DRAM1.H2
  S3 w0.079: v3(38.67,36.23) 38.15,36.23 37.78,35.86 36.16,35.86 35.91,36.12 35.91,36.75 35.81,36.85 v3(34.17,36.85)
EBI0_CA_1: length 6.2
  TOP w0.066: 35.74,36.73 35.22,36.73 SOC1.B10
  TOP w0.084: DRAM1.J2 37.93,35.91 37.58,36.26 37.26,36.26 37.09,36.08 37.09,35.7 37.02,35.64 36.83,35.64 36.54,35.93 36.54,36.12 36.7,36.27 36.86,36.27 37.04,36.45 37.04,36.67 36.89,36.82 36.61,36.82 36.42,36.62 36.42,36.45 36.32,36.35 36.12,36.35 35.74,36.73
EBI0_CA_2: length 9.5
  TOP w0.084: SOC1.A8 35.63,37.28 35.74,37.39 36.23,37.39 36.59,37.75 36.96,37.75 37.35,38.14 37.58,38.14 37.74,37.97 37.74,37.91 38.13,37.52 40.93,37.52 40.93,37.51 v3(41.13,37.51) ; v3(42.72,37.03) 42.72,37.03 42.84,36.91 43.51,36.91 43.86,36.56 DRAM1.H9
  S3 w0.079: v3(42.72,37.03) 42.53,37.22 42.23,37.51 v3(41.13,37.51)
EBI0_CA_3: length 10.8
  TOP w0.066: SOC1.B8 34.97,37.28 35.2,37.05 35.62,37.05 35.71,37.13
  TOP w0.084: DRAM1.H10 44.35,36.24 42.97,36.24 42.95,36.27 42.94,36.27 42.83,36.38 42.83,36.38 v3(42.7,36.52) ; v3(41.1,36.63) 40.84,36.88 38.18,36.88 37.98,37.09 37.98,37.41 37.89,37.5 36.72,37.5 36.35,37.13 35.71,37.13
  S3 w0.079: v3(41.1,36.63) 41.21,36.52 v3(42.7,36.52)
EBI0_CA_4: length 12.8
  TOP w0.066: SOC1.B9 35.89,36.88
  TOP w0.084: v3(41.35,36.21) 39.54,36.21 39.35,36.03 39.35,35.75 39.22,35.61 38.89,35.61 38.7,35.8 38.7,35.88 38.31,36.27 38.08,36.27 37.82,36.53 37.82,36.66 37.56,36.91 37.18,36.91 36.99,37.1 36.64,37.1 36.42,36.88 35.89,36.88 ; v3(42.63,36.05) 42.63,35.76 42.84,35.55 44.82,35.55 45.01,35.74 45.01,36.1 45.46,36.56 DRAM1.H11
  S3 w0.079: v3(41.35,36.21) 42.2,36.21 42.37,36.05 v3(42.63,36.05)
EBI0_CA_5: length 13.9
  TOP w0.084: DRAM1.J11 45.46,35.9 45.65,35.9 45.87,36.12 45.87,36.66 45.64,36.88 44.15,36.88 44.15,36.88 v3(43.99,36.88)
  S3 w0.06: 34.49,37.88 33.98,37.88 33.78,37.68 v3(33.77,37.68)
  S3 w0.079: 34.49,37.88 36.86,37.88 37.18,37.57 37.74,37.57 37.87,37.69 38.94,37.69 39.07,37.57 40.67,37.57 41.46,36.77 42.82,36.77 42.95,36.9 43.49,36.9 43.51,36.88 v3(43.99,36.88)
EBI0_CAL: length 1.2
  S3 w0.064: v3(33.37,34.88) v4(33.69,34.88)
  S6 w0.064: v1(34.39,34.77) 34.28,34.88 v4(33.69,34.88)
  BOTTOM w0.066: R1401.2 v1(34.39,34.77)
EBI0_CKE_0: length 6.9
  S3 w0.076: 34.5,37.48 33.97,37.48 v3(33.77,37.28)
  S3 w0.079: 34.5,37.48 36.39,37.48 36.7,37.17 37.9,37.17 38.19,36.88 39.11,36.88 39.39,36.6 39.39,36.45 v3(39.86,35.97)
EBI0_CKE_1: length 8.3
  S3 w0.076: v3(33.77,36.88) 33.95,37.06 34.3,37.06
  S3 w0.079: v3(40.66,35.91) 40.47,35.72 39.76,35.72 39.27,36.21 39.05,36.21 38.78,36.48 37.99,36.48 37.59,36.08 36.35,36.08 36.16,36.27 36.16,36.94 36.05,37.06 34.3,37.06
EBI0_CLK_M: length 11.3
  TOP w0.053: v3(43.69,35.92) 43.7,35.91 DRAM1.J9
  S3 w0.051: v3(33.77,36.48) 33.89,36.48 34.09,36.29 34.39,36.29 34.41,36.31
  S3 w0.053: v3(43.69,35.92) 43.59,35.92 43.53,35.86 43.53,35.67 43.34,35.48 40.74,35.48 40.24,34.98 40.23,34.98 40.21,34.96 36.52,34.96 35.18,36.31 34.41,36.31
EBI0_CLK_P: length 10.9
  S3 w0.051: v3(34.17,36.48) 34.23,36.42
  S3 w0.053: 34.23,36.42 35.23,36.42 36.57,35.08 40.17,35.08 40.69,35.6 43.3,35.6 43.41,35.72 43.41,36.09 43.36,36.14 43.26,36.14 43.22,36.11 43.22,35.91 v3(43.22,35.91)
EBI0_CS_0: length 6.4
  S3 w0.076: 34.64,37.68 v3(34.17,37.68)
  S3 w0.079: v3(39.88,36.43) 39.69,36.43 39.59,36.54 39.59,36.66 38.7,37.54 38.13,37.54 37.99,37.4 36.88,37.4 36.6,37.68 34.64,37.68
EBI0_CS_1: length 6
  S3 w0.076: 34.58,37.27 34.58,37.27 v3(34.17,37.27) ; 37.47,36.28 36.74,36.28
  S3 w0.079: 37.47,36.28 37.87,36.68 38.94,36.68 v3(39.13,36.49) ; 36.74,36.28 36.58,36.28 36.45,36.4 36.45,37.1 36.29,37.27 34.58,37.27
EBI0_DMI_0: length 5.4
  S3 w0.076: 34.32,38.48 v3(34.17,38.48)
  S3 w0.079: 34.32,38.48 36.42,38.48 36.46,38.51 36.84,38.9 37.7,38.9 38.6,39.8 v3(39.06,39.8)
EBI0_DMI_1: length 15.1
  TOP w0.084: SOC1.A11 35.72,36.08 37,34.8 40.84,34.8 41.09,35.05 41.09,35.3 41.17,35.39 41.23,35.39 41.32,35.3 41.32,35.13 41.38,35.07 41.54,35.07 41.6,35.13 41.6,35.48 41.78,35.66 41.78,39.03 41.84,39.09 41.96,39.09 42.07,38.99 42.18,38.99 42.24,39.04 42.24,39.17 42.11,39.3 42.11,39.42 42.21,39.52 42.43,39.52 42.43,39.52 44.12,39.52 44.41,39.81 44.66,39.81
EBI0_DQ0: length 5.5
  TOP w0.084: SOC1.A5 36.48,39.59 36.48,39.79 36.48,39.8 36.48,40.76 37.18,41.45 37.73,41.45 37.88,41.3 37.88,40.84 DRAM1.B2
EBI0_DQ1: length 5.5
  TOP w0.051: 35.49,38.24 35.21,38.24 34.97,38.48 SOC1.B5
  TOP w0.084: 35.49,38.24 36.69,39.44 36.69,40.39 37.04,40.75 37.58,40.75 37.98,40.35 37.98,40.1 38.26,39.81
EBI0_DQ2: length 6.2
  TOP w0.051: 35.65,38.08 35.65,38.08 SOC1.B6
  TOP w0.084: 35.65,38.08 36.61,39.04 36.98,39.41 36.98,40 37.13,40.16 37.64,40.16 37.82,39.98 37.82,39.73 38.03,39.52 38.36,39.52 38.55,39.33 38.55,38.8 DRAM1.E2
EBI0_DQ3: length 4.2
  TOP w0.084: DRAM1.F2 38.2,37.86 37.77,38.29 37.77,38.62 37.55,38.84 37.13,38.84 36.91,38.62 36.91,38.23 36.8,38.13 36.42,38.13 35.97,37.68 SOC1.A7
EBI0_DQ4: length 9.8
  S3 w0.076: 34.39,39.1 34.37,39.1 v3(34.17,38.9)
  S3 w0.079: v3(39.86,37.85) 39.86,38.51 40.11,38.76 40.11,40.54 39.85,40.79 39.58,40.79 39.4,40.97 39.14,40.97 39.11,40.94 37.71,40.94 35.88,39.1 34.39,39.1
EBI0_DQ5: length 7
  TOP w0.08: SOC1.B7 34.97,37.68 35.21,37.93 35.49,37.93
  TOP w0.084: 35.49,37.93 35.91,37.93 35.97,37.99 36.9,38.92 37.15,39.17 37.15,39.42 37.21,39.49 37.69,39.49 37.98,39.2 37.98,38.38 38.18,38.18 39.53,38.18 DRAM1.E4
EBI0_DQ6: length 6.8
  S3 w0.06: 34.67,38.68 33.97,38.68 v3(33.77,38.48)
  S3 w0.079: 34.67,38.68 36.35,38.68 36.37,38.71 37.34,39.67 37.53,39.67 37.53,39.68 37.79,39.68 37.8,39.67 37.97,39.67 38.33,40.03 39.63,40.03 v3(39.86,39.8)
EBI0_DQ7: length 6.3
  S3 w0.079: v3(34.57,38.88) 35.98,38.88 37.76,40.66 38.31,40.66 38.72,40.25 39.66,40.25 v3(39.86,40.45)
EBI0_DQ8: length 17.7
  S3 w0.076: 34.06,34.99 v3(33.77,35.28)
  S3 w0.079: 34.06,34.99 34.8,34.99 35.87,33.93 40.8,33.93 41.18,34.3 41.2,34.3 41.22,34.33 43.67,34.33 45.74,36.39 45.74,40.18 v3(45.46,40.45)
EBI0_DQ9: length 16.4
  S3 w0.076: v3(34.17,35.24) 34.62,35.24
  S3 w0.079: v3(45.46,39.81) 45.1,39.44 45.1,38.5 45.51,38.09 45.51,36.47 43.56,34.51 41.16,34.51 40.76,34.11 36,34.11 34.87,35.24 34.62,35.24
EBI0_DQ10: length 17.1
  TOP w0.08: 35.63,35.38 35.48,35.52 35.21,35.52 34.97,35.28 SOC1.B13
  TOP w0.084: 35.63,35.38 36.71,34.3 46.24,34.3 46.63,34.69 46.63,38.02 46.5,38.15 45.94,38.15 45.75,38.34 45.63,38.34 DRAM1.E11
EBI0_DQ11: length 15.2
  TOP w0.08: SOC1.B11 35.21,35.84 35.63,35.84
  TOP w0.084: 35.63,35.84 35.68,35.84 36.88,34.63 41.49,34.63 41.99,35.14 41.99,38.45 42.37,38.82 43.19,38.82 43.58,38.43 43.58,38.39 43.78,38.18 45.14,38.18 DRAM1.F11
EBI0_DQ12: length 15.1
  TOP w0.08: 35.63,35.63 35.59,35.68 SOC1.B12
  TOP w0.084: DRAM1.F9 43.73,37.99 43.35,37.99 43.16,38.18 42.69,38.18 42.4,37.89 42.4,37.61 42.34,37.55 42.23,37.55 42.17,37.5 42.17,37.42 42.23,37.37 42.34,37.37 42.4,37.31 42.4,37.24 42.34,37.18 42.23,37.18 42.17,37.13 42.17,37.05 42.23,37 42.34,37 42.4,36.95 42.4,36.87 42.34,36.82 42.23,36.82 42.17,36.76 42.17,36.69 42.23,36.63 42.34,36.63 42.4,36.58 42.4,36.5 42.34,36.45 42.23,36.45 42.17,36.4 42.17,36.32 42.23,36.27 42.34,36.27 42.4,36.21 42.4,36.14 42.34,36.08 42.23,36.08 42.17,36.03 42.17,35.95 42.23,35.9 42.34,35.9 42.4,35.84 42.4,35.77 42.34,35.71 42.23,35.71 42.17,35.66 42.17,35.58 42.23,35.53 42.34,35.53 42.4,35.48 42.4,35.4 42.34,35.35 42.23,35.35 42.17,35.29 42.17,35.22 42.23,35.16 42.34,35.16 42.4,35.11 42.4,34.78 42.08,34.47 36.8,34.47 35.63,35.63
EBI0_DQ13: length 17.4
  TOP w0.08: SOC1.A10 35.66,36.48 36.72,35.42
  TOP w0.084: 36.72,35.42 37.22,35.42 37.38,35.58 38.58,35.58 38.78,35.38 38.78,35.14 38.94,34.97 39.18,34.97 39.35,35.14 39.35,35.38 39.55,35.58 41.03,35.58 41.58,36.12 41.58,40.03 41.68,40.13 42.44,40.13 44.87,40.13 45.1,39.9 45.1,39.75 44.84,39.48 44.58,39.48 44.15,39.05 44.15,38.8 DRAM1.E9
EBI0_DQ14: length 16.2
  S3 w0.06: 34.41,35.88 33.97,35.88 v3(33.77,36.08)
  S3 w0.079: v3(43.86,39.81) 44.15,39.53 44.15,39.03 44.15,39.03 44.15,38.02 44.93,37.23 44.93,36.57 43.38,35.02 40.98,35.02 40.61,34.65 36.26,34.65 35.03,35.88 34.41,35.88
EBI0_DQ15: length 16.8
  S3 w0.079: v3(43.86,40.45) 43.64,40.23 43.64,39.25 43.3,38.91 43.3,38.46 43.4,38.36 43.4,38.36 43.59,38.18 43.59,38.18 43.64,38.12 43.64,37.89 44.53,37 44.53,36.77 44.38,36.62 43.95,36.62 43.83,36.5 43.83,36.17 44.02,35.98 44.02,35.89 43.33,35.19 40.92,35.19 40.54,34.81 36.42,34.81 35.15,36.08 v3(34.17,36.08)
EBI0_DQS_0_M: length 5.2
  S3 w0.053: v3(34.17,38.08) 34.18,38.07 36.53,38.07 37.05,38.59 38.41,38.59 38.58,38.76 38.97,38.76 v3(39.06,38.67)
EBI0_DQS_0_P: length 5.8
  S3 w0.053: v3(33.77,38.08) 33.96,38.28 34.27,38.28 34.36,38.19 36.48,38.19 37,38.71 38.37,38.71 38.53,38.87 38.94,38.87 v3(39.06,39)
EBI0_DQS_1_M: length 15.9
  S3 w0.051: 36.15,34.31 36.1,34.31 34.93,35.47 34.08,35.47 33.89,35.68 v3(33.77,35.68) ; 44.57,38.27 44.57,38.27 44.47,38.37 44.47,38.55 44.57,38.65 v3(44.68,38.65)
  S3 w0.053: 36.15,34.31 40.69,34.31 41.09,34.71 43.5,34.71 45.32,36.53 45.32,37.95 45,38.27 44.57,38.27
EBI0_DQS_1_P: length 15.6
  S3 w0.051: v3(34.17,35.67) 34.24,35.6 34.98,35.6 36.15,34.43 36.15,34.43 ; 44.57,38.15 44.52,38.15 44.35,38.32 44.35,38.6 44.56,38.81 44.56,38.88 v3(44.66,39)
  S3 w0.053: 44.57,38.15 44.95,38.15 45.19,37.9 45.19,36.58 43.45,34.83 41.04,34.83 40.63,34.43 36.15,34.43
EBI1_CA_0: length 6.1
  S3 w0.076: v3(33.77,32.08) 33.95,32.27 34.32,32.27 34.38,32.21 34.42,32.21
  S3 w0.079: 34.42,32.21 34.89,32.21 34.95,32.27 34.95,32.35 35.01,32.41 35.1,32.41 35.16,32.35 35.16,32.27 35.22,32.21 35.3,32.21 35.36,32.27 35.36,32.35 35.42,32.41 35.51,32.41 35.57,32.35 35.57,32.27 35.63,32.21 35.72,32.21 35.8,32.28 35.8,32.38 35.85,32.43 36.2,32.43 36.23,32.4 36.23,32.33 36.1,32.21 36.1,32.11 36.48,31.73 37.2,31.73 37.48,32.01 38.18,32.01 v3(38.27,31.91)
EBI1_CA_1: length 6.2
  TOP w0.066: 35.97,32.05 35.77,32.25 35.2,32.25 34.97,32.48 SOC1.B20
  TOP w0.084: 35.97,32.05 36.15,32.05 36.2,32.1 36.2,32.2 36,32.4 36,32.49 36.04,32.52 36.39,32.52 36.45,32.59 36.86,33 36.97,33 37.05,32.92 37.05,32.83 36.54,32.32 36.54,32.11 36.61,32.05 36.73,32.05 37.01,32.33 37.94,32.33 DRAM1.P2
EBI1_CA_2: length 11.7
  TOP w0.08: SOC1.A22 35.57,31.48 35.63,31.48
  TOP w0.084: 35.63,31.48 36.64,31.48 36.8,31.31 36.8,30.96 37.37,30.39 37.6,30.39 37.88,30.68 37.88,30.87 38.04,31.03 38.46,31.03 38.68,30.81 38.68,30.49 38.78,30.39 39.18,30.39 39.41,30.62 39.41,30.87 39.53,31 40.11,31 40.24,30.87 40.24,30.67 40.55,30.36 40.73,30.36 41.03,30.66 v3(41.03,30.74)
  S3 w0.079: v3(43.86,32) 43.86,31.77 43.37,31.28 43.37,31.2 43.23,31.06 41.67,31.06 41.35,30.74 v3(41.03,30.74)
EBI1_CA_3: length 11.9
  TOP w0.066: 35.7,31.69 35.47,31.92 35.2,31.92 34.97,31.68 SOC1.B22
  TOP w0.084: DRAM1.R10 44.27,32.01 43.98,31.72 43.69,31.72 43.66,31.75 v3(43.47,31.75) ; 35.7,31.69 36.7,31.69 37.34,31.05 37.62,31.05 37.82,31.25 37.82,31.32 38.14,31.65 38.57,31.65 38.61,31.6 38.61,31.38 38.98,31.01 39.16,31.01 39.44,31.29 39.44,31.34 39.74,31.65 39.98,31.65 40.17,31.45 40.17,31.3 40.42,31.05 40.81,31.05 40.84,31.08 v3(41.03,31.08)
  S3 w0.079: v3(41.03,31.08) 41.46,31.5 43.23,31.5 v3(43.47,31.75)
EBI1_CA_4: length 11.8
  TOP w0.084: v3(44.25,32.35) 45.12,32.35 DRAM1.R11 ; SOC1.B21 35.68,32.08 35.91,31.85 36.8,31.85 37.01,31.65 37.51,31.65 37.75,31.89 37.75,31.9 38.21,32.36 39.95,32.36 40.14,32.17 40.14,32.14 40.36,31.92 40.36,31.76 40.46,31.66 40.56,31.66 v3(41.06,31.66)
  S3 w0.079: v3(44.25,32.35) 43.71,32.35 43.51,32.16 41.56,32.16 v3(41.06,31.66)
EBI1_CA_5: length 14
  TOP w0.084: DRAM1.P11 45.8,32.32 45.8,31.93 45.53,31.66 44.51,31.66 44.48,31.7 v3(44.29,31.7)
  S3 w0.076: 34.64,31.23 v3(34.17,31.23)
  S3 w0.079: v3(44.29,31.7) 44.15,31.56 44.15,31.1 43.46,30.41 43.46,30.38 43.43,30.35 38.81,30.35 38.63,30.18 36.57,30.18 35.51,31.23 34.64,31.23
EBI1_CKE_0: length 8.1
  TOP w0.084: DRAM1.P4 40.14,32.66 40.26,32.54 40.26,32.35 v3(40.39,32.21)
  S3 w0.076: 34.42,31.62 34.39,31.65 v3(34.17,31.65)
  S3 w0.079: 34.42,31.62 35.38,31.62 35.39,31.61 35.74,31.61 36.23,31.12 37.43,31.12 37.78,30.77 38.44,30.77 38.8,31.14 38.8,31.38 38.93,31.51 39.15,31.51 39.27,31.63 39.36,31.63 39.94,32.21 v3(40.39,32.21)
EBI1_CKE_1: length 8.1
  TOP w0.084: v3(41.01,32.39) 40.74,32.66 DRAM1.P5
  S3 w0.076: 34.42,32.01 34.37,32.06 v3(34.17,32.06)
  S3 w0.079: v3(41.01,32.39) 40.75,32.39 40.66,32.47 39.9,32.47 39.45,32.02 38.78,32.02 38.39,31.63 38.23,31.63 38.1,31.76 37.5,31.76 37.25,31.51 36.42,31.51 35.92,32.01 35.55,32.01 35.55,32.01 34.42,32.01
EBI1_CLK_M: length 10.3
  S3 w0.051: 34.51,32.62 34.42,32.62 34.28,32.48 v3(34.17,32.48)
  S3 w0.053: 34.51,32.62 36.51,32.62 36.89,32.24 39.41,32.24 39.85,32.68 41.79,32.68 42.08,32.38 43.33,32.38 43.49,32.54 43.49,32.64 43.55,32.7 v3(43.71,32.7)
EBI1_CLK_P: length 10.5
  S3 w0.051: v3(33.77,32.48) 33.9,32.48 34.09,32.67 34.31,32.67 34.37,32.74 34.46,32.74 34.46,32.74 34.51,32.74
  S3 w0.053: v3(43.2,32.7) 43.34,32.7 43.38,32.66 43.38,32.59 43.28,32.5 42.13,32.5 41.83,32.8 39.8,32.8 39.36,32.35 36.94,32.35 36.56,32.74 34.51,32.74
EBI1_CS_0: length 7.6
  TOP w0.084: DRAM1.R4 39.86,32 v3(39.98,31.89)
  S3 w0.076: v3(33.79,31.3) 33.93,31.44 34.4,31.44 34.42,31.42
  S3 w0.079: v3(39.98,31.89) 39.88,31.79 39.8,31.79 39.33,31.31 39.33,31.21 39.33,31.13 39.17,30.97 38.95,30.97 38.94,30.96 38.94,30.96 38.31,30.34 36.7,30.34 35.61,31.42 34.42,31.42
EBI1_CS_1: length 6.5
  TOP w0.084: DRAM1.R3 v3(39.06,31.76)
  S3 w0.076: v3(33.8,31.67) 33.77,31.67 33.77,31.68 33.94,31.86 34.29,31.86 34.33,31.82 34.42,31.82
  S3 w0.079: v3(39.06,31.76) 38.8,31.76 38.52,31.49 38.52,31.18 38.34,30.99 37.82,30.99 37.5,31.32 36.34,31.32 35.84,31.81 35.47,31.81 35.46,31.82 34.42,31.82
EBI1_DMI_0: length 6.6
  S3 w0.076: v3(33.77,30.48) 33.92,30.64 34.31,30.64
  S3 w0.079: v3(39.06,28.75) 37.92,28.75 37.67,28.5 37.01,28.5 36.84,28.67 36.84,29.17 35.38,30.64 34.31,30.64
EBI1_DMI_1: length 17
  TOP w0.08: SOC1.A19 35.63,32.88
  TOP w0.084: 35.63,32.88 36.17,32.88 36.89,33.6 41.46,33.6 41.62,33.44 41.62,32.88 41.67,32.83 41.7,32.83 41.76,32.77 41.76,32.7 41.7,32.64 41.54,32.64 41.48,32.59 41.48,32.51 41.54,32.46 41.7,32.46 41.76,32.41 41.76,32.33 41.7,32.28 41.54,32.28 41.48,32.22 41.48,32.15 41.54,32.09 41.7,32.09 41.76,32.04 41.76,31.96 41.7,31.91 41.54,31.91 41.48,31.86 41.48,31.78 41.54,31.73 41.7,31.73 41.76,31.67 41.76,31.59 41.7,31.54 41.54,31.54 41.48,31.49 41.48,31.41 41.54,31.36 41.7,31.36 41.76,31.3 41.76,31.23 41.7,31.17 41.54,31.17 41.48,31.12 41.48,31.04 41.54,30.99 41.7,30.99 41.76,30.94 41.76,30.86 41.7,30.81 41.54,30.81 41.48,30.75 41.48,30.68 41.54,30.62 41.7,30.62 41.76,30.57 41.76,30.49 41.7,30.44 41.54,30.44 41.48,30.38 41.48,30.31 41.54,30.25 41.7,30.25 41.76,30.2 41.76,29.14 41.82,29.08 43.99,29.08 44.32,28.76 DRAM1.Y10
EBI1_DQ0: length 5.8
  TOP w0.084: SOC1.A25 35.66,30.48 35.81,30.33 35.81,29.84 36.61,29.04 36.61,27.9 37.34,27.17 37.62,27.17 37.79,27.34 37.79,27.63 38.26,28.11
EBI1_DQ1: length 6.1
  TOP w0.08: 35.63,30.71 35.48,30.71 35.47,30.72 35.21,30.72 SOC1.B25
  TOP w0.084: 35.63,30.71 35.97,30.71 36.08,30.6 36.08,29.91 36.84,29.15 36.84,28.13 37.15,27.82 37.58,27.82 37.85,28.09 37.85,28.35 DRAM1.Y2
EBI1_DQ2: length 6.8
  TOP w0.08: 35.63,30.88 35.32,30.88 35.32,30.88 34.97,30.88 34.97,30.88 SOC1.B24
  TOP w0.084: 35.63,30.88 36.05,30.88 36.26,30.68 36.26,30.07 37.01,29.32 37.01,28.81 37.02,28.79 37.02,28.52 37.07,28.47 37.58,28.47 37.92,28.8 37.92,28.93 38.04,29.06 38.43,29.06 38.58,29.22 38.58,29.74 DRAM1.V2
EBI1_DQ3: length 4.5
  TOP w0.08: 35.63,31.28 SOC1.A23
  TOP w0.084: 35.63,31.28 36.42,31.28 36.61,31.09 36.61,30.4 37.23,29.78 37.33,29.78 37.34,29.77 37.58,29.77 37.76,29.94 37.76,30.27 38.04,30.55 38.11,30.55 38.26,30.71
EBI1_DQ4: length 9.6
  TOP w0.084: 39.86,30.71 40.17,30.4 40.17,29.96 39.98,29.77 39.82,29.77 39.58,29.53 39.58,28.84 39.13,28.4 38.94,28.4 38.78,28.23 38.78,28.04 38.48,27.75 38.14,27.75 37.98,27.58 37.98,27.24 37.71,26.97 37.23,26.97 36.42,27.78 36.42,28.89 35.63,29.67 35.63,29.79 35.37,30.06 35.37,30.08 SOC1.A26
EBI1_DQ5: length 8.6
  TOP w0.08: 35.63,31.05 35.56,31.05 35.55,31.04 35.21,31.04 34.97,31.28 SOC1.B23
  TOP w0.084: DRAM1.V4 39.41,29.6 39.41,29.34 39.18,29.12 38.94,29.12 38.78,29.29 38.78,29.99 38.42,30.35 38.14,30.35 37.95,30.15 37.95,29.72 37.75,29.53 37.75,29.29 37.58,29.12 37.34,29.12 37.18,29.29 37.18,29.49 36.43,30.24 36.43,30.75 36.12,31.05 35.63,31.05
EBI1_DQ6: length 7.1
  S3 w0.076: 34.32,30.43 v3(34.17,30.43)
  S3 w0.079: 34.32,30.43 35.28,30.43 36.58,29.13 36.58,28.61 36.94,28.24 37.8,28.24 38.07,28.52 39.63,28.52 v3(39.86,28.75)
EBI1_DQ7: length 6.4
  S3 w0.079: v3(39.86,28.11) 39.6,28.37 38.33,28.37 37.95,27.99 36.88,27.99 36.39,28.48 36.39,29.04 35.35,30.08 v3(34.97,30.08)
EBI1_DQ8: length 17.9
  S3 w0.079: v3(34.16,33.69) 34.17,33.69 SOC1.D17 34.29,33.81 35.36,33.81 35.53,33.63 40.97,33.63 41.19,33.85 41.35,34.02 45.12,34.02 45.77,33.37 45.77,29.34 45.58,29.15 45.46,29.15 45.2,28.9 45.2,28.36 v3(45.46,28.1)
EBI1_DQ9: length 17.7
  S3 w0.079: v3(45.46,28.75) 45.93,29.22 45.93,33.42 45.18,34.18 41.28,34.18 41.12,34.02 41.12,34.02 40.88,33.78 35.67,33.78 35.46,33.99 34.07,33.99 v3(33.77,33.68)
EBI1_DQ10: length 15.1
  TOP w0.08: 35.63,33.52 35.55,33.44 35.21,33.44 SOC1.B17
  TOP w0.084: 35.63,33.52 36.24,34.13 42.37,34.13 42.68,33.82 42.68,31.32 42.94,31.06 45.6,31.06 45.8,30.86 45.8,30.14 45.71,30.06 DRAM1.V11
EBI1_DQ11: length 15.6
  TOP w0.08: SOC1.B19 34.97,32.88 35.21,33.12 35.47,33.12 35.5,33.09 35.63,33.09
  TOP w0.084: 35.63,33.09 36.06,33.09 36.09,33.12 36.1,33.12 36.76,33.79 41.67,33.79 41.98,33.48 41.98,29.62 42.11,29.49 42.6,29.49 42.88,29.77 43.39,29.77 43.48,29.85 43.48,30.08 43.82,30.42 45.18,30.42 45.46,30.71
EBI1_DQ12: length 15.5
  TOP w0.08: SOC1.B18 35.63,33.28
  TOP w0.084: 35.63,33.28 35.87,33.28 36.55,33.96 42.01,33.96 42.21,33.77 42.21,33.26 42.26,33.21 42.46,33.21 42.51,33.15 42.51,33.08 42.46,33.02 42.26,33.02 42.21,32.97 42.21,32.89 42.26,32.84 42.46,32.84 42.51,32.78 42.51,32.71 42.46,32.65 42.26,32.65 42.21,32.6 42.21,32.52 42.26,32.47 42.46,32.47 42.51,32.42 42.51,32.34 42.46,32.29 42.26,32.29 42.21,32.23 42.21,32.16 42.26,32.1 42.46,32.1 42.51,32.05 42.51,31.97 42.46,31.92 42.26,31.92 42.21,31.86 42.21,31.79 42.26,31.73 42.46,31.73 42.51,31.68 42.51,31.61 42.46,31.55 42.26,31.55 42.21,31.5 42.21,31.42 42.26,31.37 42.46,31.37 42.51,31.31 42.51,31.24 42.46,31.18 42.26,31.18 42.21,31.13 42.21,30.71 42.5,30.42 43.32,30.42 43.61,30.71 43.86,30.71
EBI1_DQ13: length 16.7
  TOP w0.08: 35.63,32.69 35.57,32.69 SOC1.A20
  TOP w0.084: 35.63,32.69 36.3,32.69 36.89,33.29 37.02,33.29 37.31,33 41.16,33 41.31,32.84 41.31,28.77 41.66,28.42 42.08,28.42 42.08,28.42 44.9,28.42 44.98,28.5 44.98,29.03 44.9,29.12 44.41,29.12 44.15,29.37 44.15,29.77 DRAM1.V9
EBI1_DQ14: length 15.4
  S3 w0.076: v3(34.17,32.87) 34.41,32.87 34.42,32.88
  S3 w0.079: v3(43.86,28.75) 43.61,29 43.61,30.35 44.37,31.11 44.37,31.42 44.54,31.59 44.54,31.81 44.51,31.84 44.51,32.46 43.63,33.34 42.8,33.34 42.41,32.96 39.69,32.96 39.29,32.55 37.04,32.55 36.65,32.94 34.48,32.94 34.42,32.88
EBI1_DQ15: length 16.8
  S3 w0.076: 34.37,33.11 34.33,33.07 33.96,33.07 v3(33.77,32.88)
  S3 w0.079: 34.37,33.11 36.72,33.11 37.12,32.71 39.22,32.71 39.63,33.12 42.36,33.12 42.73,33.49 43.72,33.49 44.67,32.53 44.67,31.91 44.7,31.87 44.7,31.57 44.91,31.37 44.91,30.58 44.22,29.89 44.22,28.46 v3(43.86,28.1)
EBI1_DQS_0_M: length 6.6
  S3 w0.051: v3(33.77,30.88) 33.96,31.04 34.43,31.04 34.45,31.02
  S3 w0.053: 34.45,31.02 35.42,31.02 37.26,29.17 38.4,29.17 38.59,29.36 38.59,29.66 38.71,29.78 38.94,29.78 v3(39.06,29.9)
EBI1_DQS_0_P: length 6.2
  S3 w0.051: v3(34.17,30.84) 34.25,30.93 34.35,30.93 34.38,30.9 34.45,30.9
  S3 w0.053: v3(39.06,29.57) 38.97,29.66 38.76,29.66 38.71,29.61 38.71,29.31 38.45,29.06 37.21,29.06 35.37,30.9 34.45,30.9
EBI1_DQS_1_M: length 15.5
  S3 w0.051: 45.18,30.13 45.18,30.13 44.84,29.79 44.77,29.79 v3(44.66,29.9) ; 34.44,33.39 34.27,33.39 v3(34.17,33.28)
  S3 w0.053: 34.44,33.39 34.55,33.39 34.58,33.36 34.58,33.28 34.61,33.25 34.65,33.25 34.68,33.28 34.68,33.36 34.71,33.39 34.75,33.39 34.78,33.36 34.78,33.28 34.81,33.25 34.86,33.25 34.89,33.28 34.89,33.36 34.91,33.38 35.22,33.38 35.32,33.27 36.94,33.27 37.33,32.88 39.08,32.88 39.52,33.32 42.14,33.32 42.52,33.7 43.8,33.7 45.18,32.32 45.18,30.13
EBI1_DQS_1_P: length 15.9
  S3 w0.051: v3(44.66,29.57) 44.77,29.67 44.89,29.67 45.3,30.08 45.3,30.13 ; 34.44,33.5 34.43,33.5 34.4,33.5 34.4,33.5 33.99,33.5 v3(33.77,33.28)
  S3 w0.053: 45.3,30.13 45.3,32.37 43.85,33.82 42.47,33.82 42.08,33.44 39.46,33.44 39.03,33 37.39,33 36.99,33.4 35.37,33.4 35.27,33.5 34.44,33.5
EMMC1_VDDI: length 5.3
  S6 w0.3: v1(23.72,24.3) 23.72,27.97 v1(23,28.7)
  BOTTOM w0.3: C2101.1 v1(23,28.7)
FAULT_N_TP: length 5.7
  S3 w0.064: v3(37.4,9.85) 37.17,10.08 37.17,10.63 37.04,10.76 36.76,10.76 36.68,10.85 36.68,11.08 36.81,11.21 36.81,12.71 37.08,12.98 37.08,14.22 36.99,14.31 v3(36.99,14.85)
FM_ANT: length 11.5
  TOP w0.066: R2909.2 6.77,61.77 7.88,60.66 10.4,60.66 11.37,61.63 12.99,61.63 U2901.7
FORCED_USB_BOOT_N: length 111.2
  TOP w0.066: v3(44.31,42.93) 44.31,42.8 43.58,42.07 21.72,42.07 20.97,41.32 20.97,37.39 22.08,36.28 22.08,33.37 21.69,32.98 21.69,29.99 v3(21.62,29.92) ; R1311.2 27.74,19.29 R1312.1 28.03,20.36 v3(28.02,20.37) 28.02,21.56 28.96,22.5 34.49,22.5 34.54,22.45 R901.2 ; v3(44.07,45) JCTL1.2 43.09,45.83 47.84,45.83 48.65,46.64 48.65,53.94 50.4,55.69 v6(50.8,55.69)
  S3 w0.064: v4(19.15,16.9) 20.18,16.9 20.99,17.71 20.99,18.39 23,20.4 27.1,20.4 27.22,20.52 27.86,20.52 v3(28.02,20.37) ; v3(44.07,45) 44.07,43.17 v3(44.31,42.93) ; v3(26.17,29.68) 26,29.51 22.09,29.51 21.68,29.92 v3(21.62,29.92) 21.41,29.92 20.81,29.32 v4(19.45,29.32) 19.41,29.32 19.32,29.24 9.29,29.24 v4(8.1,30.43)
  S6 w0.064: v4(8.1,30.43) 8.09,30.42 v1(7.82,30.42) ; v4(19.45,29.32) 19.08,28.95 19.08,27.22 19.6,26.7 19.6,17.35 v4(19.15,16.9)
  BOTTOM w0.066: v6(50.8,55.69) 50.86,55.75 TP2611.1 ; R2517.2 v1(7.82,30.42)
